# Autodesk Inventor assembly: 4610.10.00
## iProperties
Shininess: 64.0
Length Units: 11269
Angle Units: 11279
Time Units: 11290
Mass Units: 11283
Length Display Precision: 3
Angle Display Precision: 2
Compacted: True
Created: 2004-11
Part Number: 4610.10.00
Document SubType Name: Assembly
Description: Nachfüllautomat
Designer: sschwock
Manufacturer: Standard
Standards Organization: Custom
Density: 0.0
Volumn: 0.0
Area: 0.0
PropertySet Name: Model Information
Control State: 0
Master: False
Checked Out: False
Author: sschwock
